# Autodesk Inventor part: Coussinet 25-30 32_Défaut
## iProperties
Shininess: 64.0
Length Units: 11269
Angle Units: 11279
Time Units: 11290
Mass Units: 11283
Length Display Precision: 3
Angle Display Precision: 2
Compacted: True
Part Number: Coussinet 25-30 32_Défaut
Document SubType Name: Modeling
Created: 2006-11
Material: Par défaut
Designer: profs_sti
Density: 0.0
Volumn: 0.0
Area: 0.0
PropertySet Name: Model Information
Control State: 0
Master: False
Checked Out: False
Author: profs_sti
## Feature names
1. Base1
